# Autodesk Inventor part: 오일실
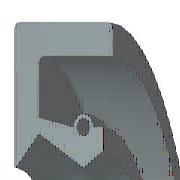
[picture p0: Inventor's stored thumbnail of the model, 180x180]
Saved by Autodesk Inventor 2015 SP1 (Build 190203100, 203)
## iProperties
Created: 2009-02
Part Number: 오일실
Material: 고무
Description: 오일-실
Document SubType Name: Modeling
Standard: KS B 2804
Designer: SeoGD™
Standards Organization: KS
Language: ko-KR
Size Designation: D - 10 20 7
Categories: <MemberInstance><Categories><Category DisplayName="샤프트 부품" InternalName="7f7aeb1f-a693-4053-b835-cee3144e0d98" Mnemonic="SHFT"><Category DisplayName="실링" Intern
Density: 0.93 g/cm^3
Appearance: 고무 - 검은색 - 버전 1.1
Mass: 1.11329 g
Surface Area: 16.3871 cm^2
Volume: 1.19708 cm^3
IsCustomPart: 0
Author: SeoGD™
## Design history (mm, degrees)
revolve "본체" stored, may be unused: angle "d17" = 90 deg
revolve "스프링1" stored, may be unused: angle "d18" = 90 deg
body "Solid1"
sketch "스케치1"
  geometry: L1 (0, 10)-(7, 10); L2 (7, 8.25)-(1.75, 8.25); L3 (1.75, 6.75)-(4.9, 5); L4 (4.9, 5)-(0, 5); L5 (0, 0)-(9.586, 0) reference; L6 (4.9, 5)-(6.3, 5.875); L7 (0, 18)-(0, -3) reference; L8 (-1.941, 0)-(11.507, 0) reference; L9 (4.2, 7.1)-(1.75, 7.59); L10 (1.75, 7.59)-(1.75, 8.25); L11 (0, 10)-(0, 5.088); L12 (4.9, 5)-(0, 5); L13 (1.75, 6.75)-(0.152, 5.028); L14 (7, 10)-(7, 8.25); L15 (5.6, 7.1)-(6.3, 7.1); L16 (6.3, 7.1)-(6.3, 5.875); C1 r 0.455 at (4.9, 7.1); A1 r 0.7 centre (4.9, 7.1) between (5.6, 7.1) and (4.2, 7.1); A2 r 0.088 centre (0.088, 5.088) between (0, 5.088) and (0.152, 5.028); 1 further point
  constraints: 28 end point, 5 horizontal alignment, 5 point on line, 4 point on circle, 4 vertical alignment, 3 centre point, 3 tangent, 2 collinear, 2 horizontal, 2 perpendicular, 1 coincident, 1 parallel
  dimensions: "d0" = 20 diameter of L1 L5 (= SD2); "d1" = 1.75 distance of L1.end L2.start (= SD); "d2" = 0.91 diameter of C1 (= SPDI); "d3" = 1.4 diameter of A1 (= SPDA); "d4" = 10 diameter of L3.end L5 (= NND); "d5" = 13.5 diameter of L3.start L5 (= TKDM); "d7" = 15.18 diameter of L9.end L5 (= TKDM + 0.24 x SWDT); "d8" = 1.75 distance between parallel lines of L11 L10 (= SD); "d9" = 4.9 distance from line of L11 C1.centre (= SPDST); "d10" = 14.2 diameter of C1.centre L5 (= HLDM); "d11" = 0.0875 radius of A2 (= 0.25 x LAB); "d12" = 6.3 distance between parallel lines of L11 L16 (= SDI); "d13" = 11.75 diameter of L6.end L5 (= ABDM); "d14" = 7 distance from line of L11 L1.end (= SWDT)
fillet "모깎기1" dims "d6" = 0.3 (= RR)
other parameters: "SD2" = 20 [user parameter; used in 1 equation term], "SWDT" = 7 [user parameter; used in 2 equation terms], "RR" = 0.3 [user parameter; used in 1 equation term], "SD" = 1.75 [user parameter; used in 2 equation terms], "NND" = 10 [user parameter; used in 1 equation term], "SPDA" = 1.4 [user parameter; used in 1 equation term], "SPDI" = 0.91 [user parameter; used in 1 equation term], "TKDM" = 13.5 [user parameter; used in 2 equation terms], "HLDM" = 14.2 [user parameter; used in 1 equation term], "ABDM" = 11.75 [user parameter; used in 1 equation term], "SDI" = 6.3 [user parameter; used in 1 equation term], "SPDST" = 4.9 [user parameter; used in 1 equation term], "LAB" = 0.35 [user parameter; used in 1 equation term], "d15" = 0, "d16" = 0, "d19" = 0
